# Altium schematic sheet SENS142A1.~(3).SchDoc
size 431 x 279 mm; Date: Not shown in title block; ApprovedBy: Not shown in title block; CheckedBy: Not shown in title block; Author: Not shown in title block; CompanyName: Not shown in title block; Engineer: Not shown in title block; Organization: Not shown in title block; Address1: Not shown in title block; Address2: Not shown in title block; Address3: Not shown in title block; Address4: Not shown in title block; DocumentNumber: 2; Revision: Use project parameter SCH_Rev; SheetNumber: 2; SheetTotal: 3; PageSetup: Record=PageOptions¦CenterHorizontal=True¦CenterVertical=True¦PrintScale=1.00¦XCorrection=1.00¦YCorrection=1.00¦PrintKind=0¦BorderSize=5000000¦LeftOffset=0¦BottomOffset=0¦Orientation=2¦PaperLength=1000¦PaperWidth=1000¦Scale=100¦PaperSource=15¦PrintQuality=600¦MediaType=1¦DitherType=10¦PaperKind=Letter¦PrintScaleMode=1
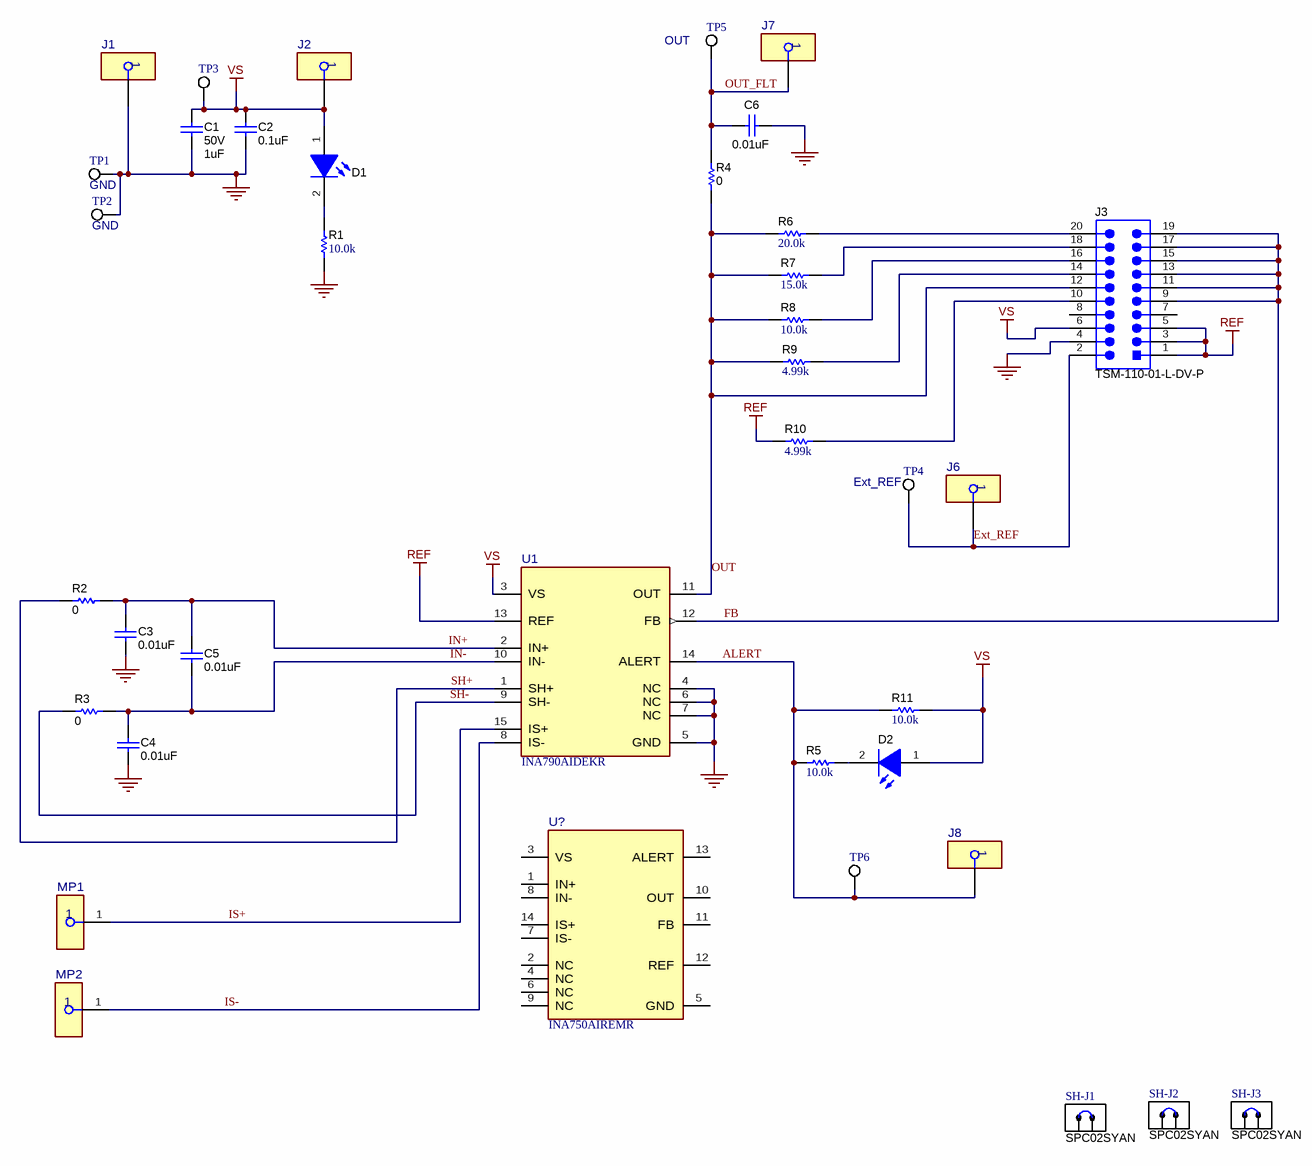
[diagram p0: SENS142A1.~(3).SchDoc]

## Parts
C1  VDC_V: 50V  ValueDisplayed: 1uF  [0603]  (hidden comment: C1608X6S1H105K080AC)
C2  ValueDisplayed: 0.1uF  [0402]  (hidden comment: GRM155R71H104ME14D)
C3  ValueDisplayed: 0.01uF  [0402]  (hidden comment: CGA2B3X7S2A103K050BB)
C4  ValueDisplayed: 0.01uF  [0402]  (hidden comment: CGA2B3X7S2A103K050BB)
C5  ValueDisplayed: 0.01uF  [0402]  (hidden comment: CGA2B3X7S2A103K050BB)
C6  ValueDisplayed: 0.01uF  [0402]  (hidden comment: CGA2B3X7S2A103K050BB)
D1  POWER  [VAOL-0805_White]  (value not drawn)
D2  ALERT  [VAOL-0805_White]  (value not drawn)
J1  (no value)  [FP-3-331272-8_PIN_RCPT-MFG]
J2  (no value)  [FP-3-331272-8_PIN_RCPT-MFG]
J3  TSM-110-01-L-DV-P  [CONN_TSM-110-01-T-DV-P]
J6  (no value)  [FP-3-331272-8_PIN_RCPT-MFG]
J7  (no value)  [FP-3-331272-8_PIN_RCPT-MFG]
J8  (no value)  [FP-3-331272-8_PIN_RCPT-MFG]
MP1  LAMA6-14-QY  [FP-LAMA6-14-QY_TERMINAL_CONN-MFG]  (value not drawn)
MP2  LAMA6-14-QY  [FP-LAMA6-14-QY_TERMINAL_CONN-MFG]  (value not drawn)
R1  ValueDisplayed: 10.0k  [0402]  (hidden comment: CRCW040210K0FKED)
R2  ValueDisplayed: 0  [0402]  (hidden comment: RC0402JR-070RL)
R3  ValueDisplayed: 0  [0402]  (hidden comment: RC0402JR-070RL)
R4  ValueDisplayed: 0  [0402]  (hidden comment: RC0402JR-070RL)
R5  ValueDisplayed: 10.0k  [0402]  (hidden comment: CRCW040210K0FKED)
R6  ValueDisplayed: 20.0k  [0402]  (hidden comment: CRCW040220K0FKED)
R7  ValueDisplayed: 15.0k  [0402]  (hidden comment: CRCW040215K0FKED)
R8  ValueDisplayed: 10.0k  [0402]  (hidden comment: CRCW040210K0FKED)
R9  ValueDisplayed: 4.99k  [0402]  (hidden comment: CRCW04024K99FKED)
R10  ValueDisplayed: 4.99k  [0402]  (hidden comment: CRCW04024K99FKED)
R11  ValueDisplayed: 10.0k  [0402]  (hidden comment: CRCW040210K0FKED)
SH-J1  SPC02SYAN  [SPC02SYAN]
SH-J2  SPC02SYAN  [SPC02SYAN]
SH-J3  SPC02SYAN  [SPC02SYAN]
TP1  GND  [Testpoint_Keystone_Miniature]
TP2  GND  [Testpoint_Keystone_Miniature]
TP3  VS  [Testpoint_Keystone_Miniature]  (value not drawn)
TP4  Ext_REF  [Testpoint_Keystone_Miniature]
TP5  OUT  [Testpoint_Keystone_Miniature]
TP6  (no value)  [Testpoint_Keystone_Miniature]
U1  INA790AIDEKR  [DEK0015A-MFG]
U?  INA750AIREMR  [REM0014B-MFG]

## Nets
GND: C1.2 C2.2 C3.2 C4.2 C6.1 J1.1 J3.4 R1.1 TP1.1 TP2.1 U1.4(NC) U1.5(GND) U1.6(NC) U1.7(NC)
REF: J3.1 J3.3 J3.5 R10.1 U1.13(REF)
VS: C1.1 C2.1 D1.1(A) D2.1(A) J2.1 J3.6 R11.1 TP3.1 U1.3(VS)
ALERT: J8.1 R5.2 R11.2 TP6.1 U1.14(ALERT)
Ext_REF: J3.2 J6.1 TP4.1
FB: J3.9 J3.11 J3.13 J3.15 J3.17 J3.19 U1.12(FB)
IN+: C3.1 C5.1 R2.2 U1.2(IN+)
IN-: C4.1 C5.2 R3.2 U1.10(IN-)
IS+: MP1.1 U1.15(IS+)
IS-: MP2.1 U1.8(IS-)
OUT: J3.12 R4.1 R6.1 R7.1 R8.2 R9.1 U1.11(OUT)
OUT_FLT: C6.2 J7.1 R4.2 TP5.1
SH+: R2.1 U1.1(SH+)
SH-: R3.1 U1.9(SH-)
NetD1_2: D1.2(K) R1.2
NetD2_2: D2.2(K) R5.1
NetJ3_10: J3.10 R10.2
NetJ3_14: J3.14 R9.2
NetJ3_16: J3.16 R8.1
NetJ3_18: J3.18 R7.2
NetJ3_20: J3.20 R6.2

Not connected (* = marked no-connect by the designer): J3 7 8; U? 1(IN+) 2(NC) 3(VS) 4(NC) 5(GND) 6(NC) 7(IS-) 8(IN-) 9(NC) 10(OUT) 11(FB) 12(REF) 13(ALERT) 14(IS+)

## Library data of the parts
C1 = CMP-0007029-4: CAP, CERM, 1 uF, 50 V, +/- 10%, X6S, 0603; Manufacturer: TDK; TaMin_C: -55°C; ESR_ohm: 5.522m; Polarized: N; SizeAreaWB_mm2: 4.68; Value1: 0.005522 ohm; U/M: EA; Value: 1uF; TaMax_C: 105°C; SizeZ_mm: 1; SizeX_mm: 1.6; SizeY_mm: 0.8; SizeArea_mm2: 1.28; Cap_F: 1µF; IRMS_A: 2.21617A; AEC Category: Q200
C2 = CMP-0006675-2: CAP, CERM, 0.1 uF, 50 V, +/- 20%, X7R, 0402; Manufacturer: MuRata; Polarized: N; Value: 0.1uF; U/M: EA; Cap_F: 100nF; Value1: Unknown; VDC_V: 50V; TaMin_C: -55°C; TaMax_C: 125°C; SizeArea_mm2: 0.5; SizeAreaWB_mm2: 3; SizeX_mm: 1; SizeZ_mm: 0.6; AEC Category: Q200
C3-C6 = CMP-0006333-1: CAP, CERM, 0.01 uF, 100 V, +/- 10%, X7S, AEC-Q200 Grade 1, 0402; Manufacturer: TDK; TaMin_C: -55°C; ESR_ohm: 0.410191; Polarized: N; SizeAreaWB_mm2: 3; Value1: 0.410191 ohm; U/M: EA; Value: 0.01uF; TaMax_C: 125°C; SizeZ_mm: 0.6; SizeX_mm: 1; SizeY_mm: 0.5; Value2: 100V; AEC Qualified: Y; Cap_F: 10nF; IRMS_A: 291.729mA; AEC Category: Q200
D1 D2 = CMP-0002885-2: LED, White, SMD; PartNumber: VAOL-S8WR4; Manufacturer: Visual Communications Company, LLC; Type: InGaN; Value1: W; Io_A: 5mA; Vf_V: 2.925V
J1 J2 J6-J8 = CMP-0086763-1: CONN PIN RCPT .018-.021 SOLDER; PartNumber: 3-331272-8; Manufacturer: TE Connectivity; ContactFinish: Gold,Nickel; Current_A: 5A
J3 = CMP-0075600-2: Header, 2.54mm, 10x2, Gold, SMT; Manufacturer: Samtec; Pitch_mm: 2.54; Gender: Male; Cert_CSA: Y; Green_REACh: Passed; Current_A: 5.4A; Voltage_V: 475V; Shrouded: N; Green_Lifecycle: Active; Row_Count: 2
MP1 MP2 = CMP-0091352-2: Terminal Connector Rectangular Lug, Grounding 6-14 AWG 1/4 Stud; Manufacturer: Panduit; SizeZ_mm: 0.54inch; AEC Qualified: No; Is Female: yes
R1 R5 R8 R11 = CMP-0025958-3: RES, 10.0 k, 1%, 0.063 W, AEC-Q200 Grade 0, 0402; Manufacturer: Vishay-Dale; Power_W: 63mW; TempCo: 100 ppm/C; Value_Code: 10k0; Value: 10.0k; EIA_Code: E96; Res_ohm: 10k; SizeX_mm: 1; SizeY_mm: 0.5; SizeZ_mm: 0.6; Value2: 0.063W; AEC Qualified: Y; VDC_V: 50V; AEC Category: Q200; AEC Grade: 0
R2-R4 = CMP-0027004-2: RES, 0, 5%, 0.063 W, 0402; Manufacturer: Yageo America; Power_W: 63mW; TempCo: 200 ppm/C; Value_Code: 0000; U/M: EA; Value: 0; EIA_Code: E24; SizeX_mm: 1; SizeY_mm: 0.5; SizeZ_mm: 0.6; Value2: 0.063W; VDC_V: 50V; AEC Category: Q200
R6 = CMP-0026162-1: RES, 20.0 k, 1%, 0.063 W, 0402; Manufacturer: Vishay-Dale; Power_W: 63mW; TempCo: 100 ppm/C; Value_Code: 20k0; U/M: EA; Value: 20.0k; EIA_Code: E96; Res_ohm: 20k; SizeX_mm: 1; SizeY_mm: 0.5; SizeZ_mm: 0.6; Value2: 0.063W; VDC_V: 50V; AEC Category: Q200
R7 = CMP-0026027-2: RES, 15.0 k, 1%, 0.063 W, 0402; Manufacturer: Vishay-Dale; Power_W: 63mW; TempCo: 100 ppm/C; Value_Code: 15k0; U/M: EA; Value: 15.0k; EIA_Code: E96; Res_ohm: 15k; SizeX_mm: 1; SizeY_mm: 0.5; SizeZ_mm: 0.6; Value2: 0.063W; VDC_V: 50V; AEC Category: Q200
R9 R10 = CMP-0026414-1: RES, 4.99 k, 1%, 0.063 W, 0402; Manufacturer: Vishay-Dale; Power_W: 63mW; TempCo: 100 ppm/C; Value_Code: 4k99; U/M: EA; Value: 4.99k; EIA_Code: E96; SizeX_mm: 1; SizeY_mm: 0.5; SizeZ_mm: 0.6; Value2: 0.063W; VDC_V: 50V; AEC Category: Q200
SH-J1-SH-J3 = CMP-0003642-1: Shunt, 100mil, Flash Gold, Black; Manufacturer: Sullins Connector Solutions; Value: 1x2
TP1-TP6 = CMP-0055152-1: Test Point, Miniature, SMT; Manufacturer: Keystone; CNHeader: FALSE; Green_Lifecycle: Active; Green_REACh: Passed; CT: TRUE
U1 = CMP-0034221-1: Manufacturer: Texas Instruments; SizeZ_mm: 1mm; Standoff Height: 0mm
U? = CMP-0122809-1: -4V to 110V, Bidirectional, Ultra-Precise, Current Sense Amplifier with Enhanced PWM Rejection and 35A EZShuntTM Technology; Manufacturer: Texas Instruments; SizeZ_mm: 1mm; AEC Qualified: No; Bandwidth: 1MHz; Input Offset Voltage: 65mV; Max Supply Voltage: 5.5V; Min Supply Voltage: 2.7V; Nominal Supply Current: 3.5mA; Number Of Channels: 1; Output Current Per Channel: 25A; Response Time: 2.5us; Standoff Height: 0mm; TaMax_C: +125°C; TaMin_C: -40°C; TJmax_C: +150°C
